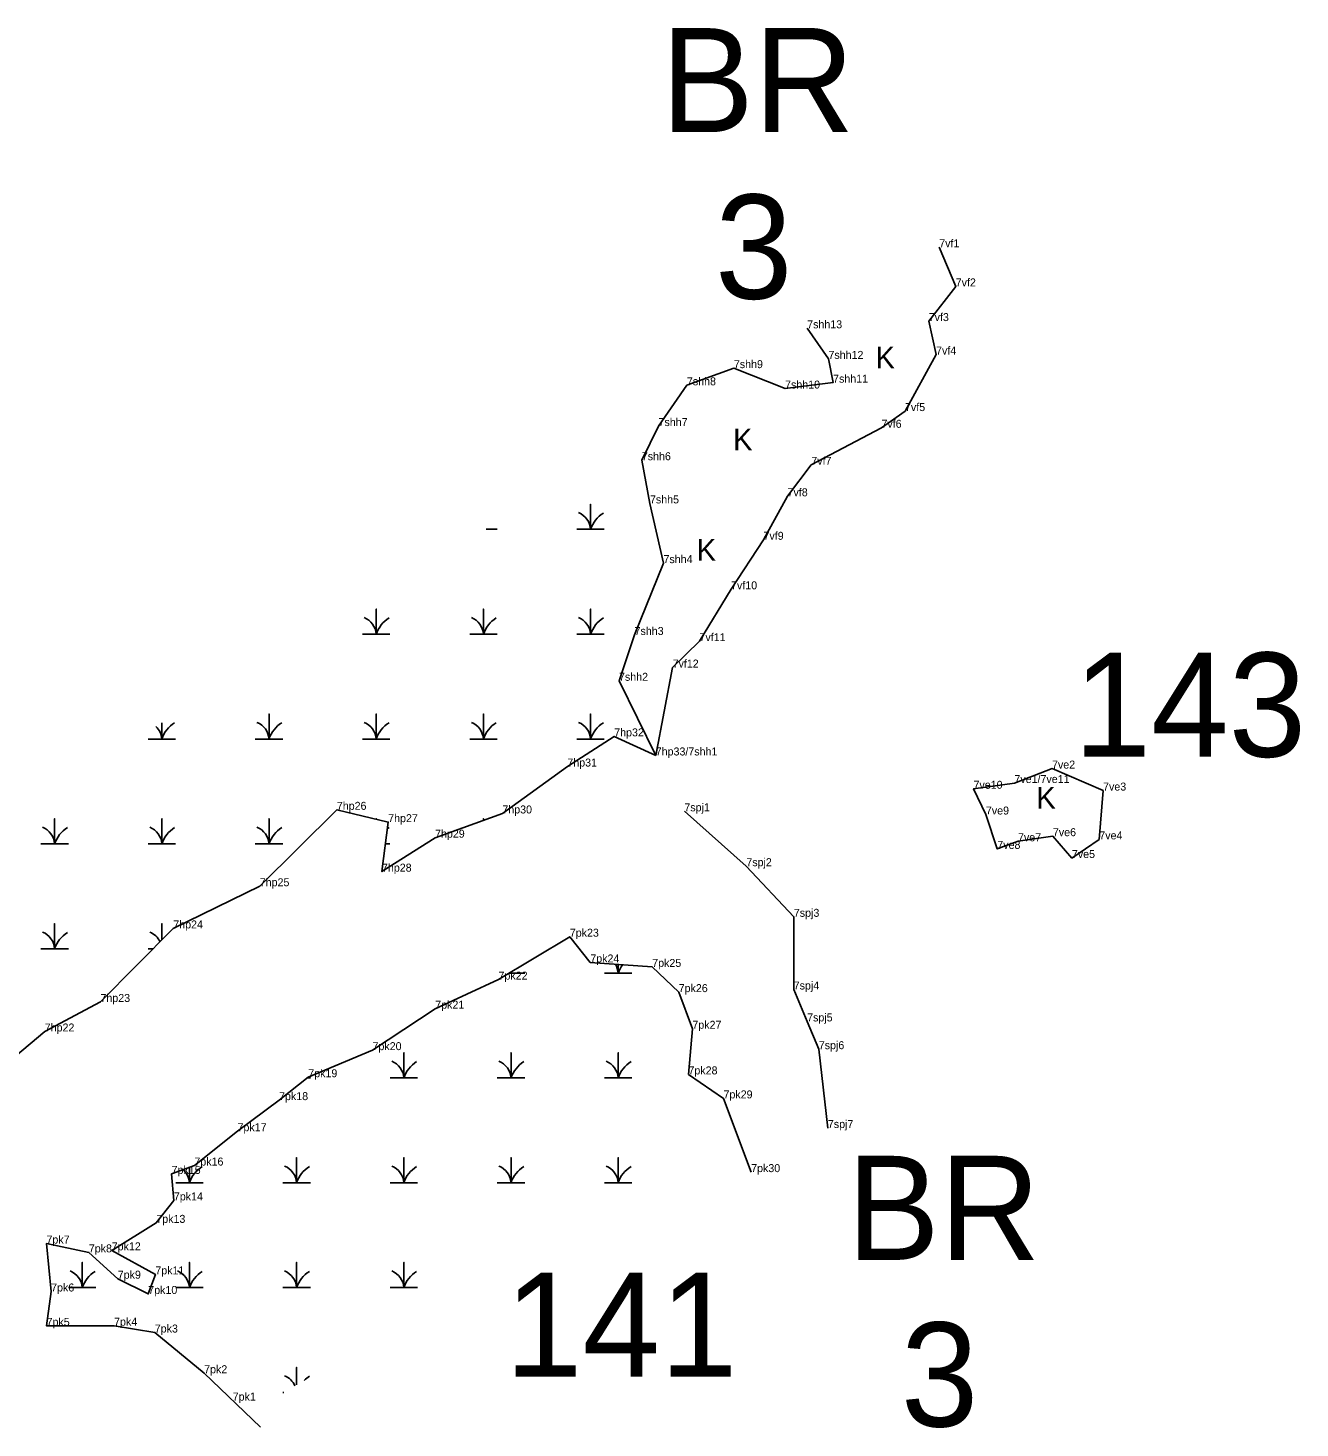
# Model space of a CAD drawing. Extents: x 2072529 to 2268796, y 436423 to 470397.
# Drawn here: x 2166130 to 2166928, y 441934 to 442813 of the extents above; entities that cross this region are included whole.
import ezdxf

# ---------------------------------------------------------------- set-up
doc = ezdxf.new("R2010")
doc.units = 0
for name, color, linetype in [('Default', 7, 'Continuous'), ('Exist Environmental Wetland Boundary', 7, 'Continuous'), ('Exist Environmental Wetland Boundary Cogo Comment', 7, 'Continuous'), ('Exist Environmental Wetland Boundary Cogo Point CELL', 7, 'Continuous'), ('Exist Hydro Jurisdictional Stream or Body of Water NEU Mitigable', 7, 'Continuous'), ('Exist Hydro Jurisdictional Stream or Body of Water NEU Mitigable Cogo Comment', 7, 'Continuous'), ('Exist Hydro Swamp or Marsh', 7, 'Continuous')]:
    doc.layers.add(name, color=color, linetype=linetype)

msp = doc.modelspace()

# ---------------------------------------------------------------- linework, layer by layer
at = {"layer": 'Exist Environmental Wetland Boundary'}
for points in [[(2166523.46, 442356.4), (2166534.04, 442411.56), (2166550.9, 442428.12), (2166570.7, 442460.66), (2166591.07, 442491.73), (2166606.15, 442519.05), (2166621.06, 442538.77), (2166665.06, 442562.01), (2166679.83, 442572.5), (2166699.33, 442607.99), (2166694.72, 442628.97), (2166711.66, 442650.73), (2166701.31, 442675.29)], [(2166103.24, 442152.13), (2166140.13, 442183.19), (2166175.08, 442201.73), (2166220.76, 442247.86), (2166275.02, 442274.32), (2166323.39, 442322.28), (2166355.6, 442314.55), (2166351.69, 442283.5), (2166385.01, 442304.8), (2166427.23, 442320.01), (2166467.99, 442349.45), (2166497.41, 442368.38), (2166523.46, 442356.4)], [(2166275.52, 441934.8), (2166240.13, 441968.75), (2166209.16, 441994.29), (2166183.64, 441998.59), (2166141.28, 441998.44), (2166144.14, 442020.04), (2166141.2, 442050.11), (2166167.79, 442044.56), (2166185.94, 442028.08), (2166205.06, 442018.49), (2166209.52, 442030.78), (2166182.15, 442045.86), (2166210.12, 442063.11), (2166221.13, 442077.18), (2166219.71, 442093.84), (2166234, 442099.06), (2166261.07, 442120.62), (2166287.14, 442140.11), (2166305.45, 442154.48), (2166345.76, 442171.48), (2166385.12, 442197.5), (2166424.81, 442215.74), (2166469.55, 442242.67), (2166482.4, 442226.51), (2166521.24, 442223.71), (2166537.85, 442207.9), (2166546.44, 442184.9), (2166543.98, 442156.26), (2166565.97, 442141.21), (2166583.32, 442094.94)]]:
    msp.add_lwpolyline(points, dxfattribs=at)
msp.add_lwpolyline([(2166748.49, 442339.11), (2166772.08, 442348.17), (2166804.11, 442334.36), (2166801.74, 442303.75), (2166784.54, 442292.04), (2166772.63, 442305.74), (2166750.73, 442302.56), (2166737.74, 442297.78), (2166730.6, 442319.35), (2166722.82, 442335.49)], close=True, dxfattribs=at)
at = {"layer": 'Exist Environmental Wetland Boundary Cogo Point CELL'}
for p, q in [((2166701.31, 442675.29), (2166701.31, 442675.29)), ((2166711.66, 442650.73), (2166711.66, 442650.73)), ((2166618.45, 442624.44), (2166618.45, 442624.44)), ((2166694.72, 442628.97), (2166694.72, 442628.97)), ((2166631.81, 442605.23), (2166631.81, 442605.23)), ((2166699.33, 442607.99), (2166699.33, 442607.99)), ((2166572.48, 442599.44), (2166572.48, 442599.44)), ((2166543.01, 442588.68), (2166543.01, 442588.68)), ((2166604.59, 442586.62), (2166604.59, 442586.62)), ((2166634.71, 442590.33), (2166634.71, 442590.33)), ((2166679.83, 442572.5), (2166679.83, 442572.5)), ((2166525.21, 442563.09), (2166525.21, 442563.09)), ((2166665.06, 442562.01), (2166665.06, 442562.01)), ((2166514.72, 442541.65), (2166514.72, 442541.65)), ((2166621.06, 442538.77), (2166621.06, 442538.77)), ((2166606.15, 442519.05), (2166606.15, 442519.05)), ((2166519.83, 442514.55), (2166519.83, 442514.55)), ((2166591.07, 442491.73), (2166591.07, 442491.73)), ((2166528.31, 442477.08), (2166528.31, 442477.08)), ((2166570.7, 442460.66), (2166570.7, 442460.66)), ((2166510.17, 442432), (2166510.17, 442432)), ((2166550.9, 442428.12), (2166550.9, 442428.12)), ((2166534.04, 442411.56), (2166534.04, 442411.56)), ((2166500.4, 442403.25), (2166500.4, 442403.25)), ((2166497.41, 442368.38), (2166497.41, 442368.38)), ((2166467.99, 442349.45), (2166467.99, 442349.45)), ((2166523.46, 442356.4), (2166523.46, 442356.4)), ((2166523.46, 442356.4), (2166523.46, 442356.4)), ((2166772.08, 442348.17), (2166772.08, 442348.17)), ((2166722.82, 442335.49), (2166722.82, 442335.49)), ((2166748.49, 442339.11), (2166748.49, 442339.11)), ((2166804.11, 442334.36), (2166804.11, 442334.36)), ((2166323.39, 442322.28), (2166323.39, 442322.28)), ((2166355.6, 442314.55), (2166355.6, 442314.55)), ((2166427.23, 442320.01), (2166427.23, 442320.01)), ((2166541.41, 442321.34), (2166541.41, 442321.34)), ((2166730.6, 442319.35), (2166730.6, 442319.35)), ((2166772.63, 442305.74), (2166772.63, 442305.74)), ((2166385.01, 442304.8), (2166385.01, 442304.8)), ((2166737.74, 442297.78), (2166737.74, 442297.78)), ((2166750.73, 442302.56), (2166750.73, 442302.56)), ((2166801.74, 442303.75), (2166801.74, 442303.75)), ((2166784.54, 442292.04), (2166784.54, 442292.04)), ((2166351.69, 442283.5), (2166351.69, 442283.5)), ((2166580.28, 442286.91), (2166580.28, 442286.91)), ((2166275.02, 442274.32), (2166275.02, 442274.32)), ((2166610.1, 442255.15), (2166610.1, 442255.15)), ((2166220.76, 442247.86), (2166220.76, 442247.86)), ((2166469.55, 442242.67), (2166469.55, 442242.67)), ((2166482.4, 442226.51), (2166482.4, 442226.51)), ((2166521.24, 442223.71), (2166521.24, 442223.71)), ((2166424.81, 442215.74), (2166424.81, 442215.74)), ((2166610.01, 442209.54), (2166610.01, 442209.54)), ((2166175.08, 442201.73), (2166175.08, 442201.73)), ((2166537.85, 442207.9), (2166537.85, 442207.9)), ((2166385.12, 442197.5), (2166385.12, 442197.5)), ((2166140.13, 442183.19), (2166140.13, 442183.19)), ((2166546.44, 442184.9), (2166546.44, 442184.9)), ((2166618.43, 442189.5), (2166618.43, 442189.5)), ((2166345.76, 442171.48), (2166345.76, 442171.48)), ((2166625.75, 442172.08), (2166625.75, 442172.08)), ((2166543.98, 442156.26), (2166543.98, 442156.26)), ((2166305.45, 442154.48), (2166305.45, 442154.48)), ((2166287.14, 442140.11), (2166287.14, 442140.11)), ((2166565.97, 442141.21), (2166565.97, 442141.21)), ((2166631.45, 442122.62), (2166631.45, 442122.62)), ((2166261.07, 442120.62), (2166261.07, 442120.62)), ((2166234, 442099.06), (2166234, 442099.06)), ((2166583.32, 442094.94), (2166583.32, 442094.94)), ((2166219.71, 442093.84), (2166219.71, 442093.84)), ((2166221.13, 442077.18), (2166221.13, 442077.18)), ((2166210.12, 442063.11), (2166210.12, 442063.11)), ((2166141.2, 442050.11), (2166141.2, 442050.11)), ((2166167.79, 442044.56), (2166167.79, 442044.56)), ((2166182.15, 442045.86), (2166182.15, 442045.86)), ((2166185.94, 442028.08), (2166185.94, 442028.08)), ((2166209.52, 442030.78), (2166209.52, 442030.78)), ((2166144.14, 442020.04), (2166144.14, 442020.04)), ((2166205.06, 442018.49), (2166205.06, 442018.49)), ((2166141.28, 441998.44), (2166141.28, 441998.44)), ((2166183.64, 441998.59), (2166183.64, 441998.59)), ((2166209.16, 441994.29), (2166209.16, 441994.29)), ((2166240.13, 441968.75), (2166240.13, 441968.75)), ((2166258.04, 441951.57), (2166258.04, 441951.57))]:
    msp.add_line(p, q, dxfattribs=at)
at = {"layer": 'Exist Hydro Jurisdictional Stream or Body of Water NEU Mitigable'}
for points in [[(2166618.45, 442624.44), (2166631.81, 442605.23), (2166634.71, 442590.33), (2166604.59, 442586.62), (2166572.48, 442599.44), (2166543.01, 442588.68), (2166525.21, 442563.09), (2166514.72, 442541.65), (2166519.83, 442514.55), (2166528.31, 442477.08), (2166510.17, 442432), (2166500.4, 442403.25), (2166523.46, 442356.4)], [(2166541.41, 442321.34), (2166580.28, 442286.91), (2166610.1, 442255.15), (2166610.01, 442209.54), (2166618.43, 442189.5), (2166625.75, 442172.08), (2166631.45, 442122.62)]]:
    msp.add_lwpolyline(points, dxfattribs=at)
at = {"layer": 'Exist Hydro Swamp or Marsh'}
for points in [[(2166473.98, 442498.29), (2166482.59, 442498.29), (2166482.59, 442514.07), (2166482.59, 442498.29), (2166491.19, 442498.29)], [(2166417.03, 442498.29), (2166423.94, 442498.29)], [(2166339.48, 442432.49), (2166348.09, 442432.49), (2166348.09, 442448.27), (2166348.09, 442432.49), (2166356.69, 442432.49)], [(2166406.73, 442432.49), (2166415.34, 442432.49), (2166415.34, 442448.27), (2166415.34, 442432.49), (2166423.94, 442432.49)], [(2166473.98, 442432.49), (2166482.59, 442432.49), (2166482.59, 442448.27), (2166482.59, 442432.49), (2166491.19, 442432.49)], [(2166204.98, 442366.69), (2166213.59, 442366.69), (2166213.59, 442376.81)], [(2166213.59, 442376.81), (2166213.59, 442366.69), (2166222.19, 442366.69)], [(2166272.23, 442366.69), (2166280.84, 442366.69), (2166280.84, 442382.47), (2166280.84, 442366.69), (2166289.44, 442366.69)], [(2166339.48, 442366.69), (2166348.09, 442366.69), (2166348.09, 442382.47), (2166348.09, 442366.69), (2166356.69, 442366.69)], [(2166406.73, 442366.69), (2166415.34, 442366.69), (2166415.34, 442382.47), (2166415.34, 442366.69), (2166423.94, 442366.69)], [(2166473.98, 442366.69), (2166482.59, 442366.69), (2166482.59, 442382.47), (2166482.59, 442366.69), (2166491.19, 442366.69)], [(2166137.73, 442300.89), (2166146.34, 442300.89), (2166146.34, 442316.67), (2166146.34, 442300.89), (2166154.94, 442300.89)], [(2166204.98, 442300.89), (2166213.59, 442300.89), (2166213.59, 442316.67), (2166213.59, 442300.89), (2166222.19, 442300.89)], [(2166272.23, 442300.89), (2166280.84, 442300.89), (2166280.84, 442316.67), (2166280.84, 442300.89), (2166289.44, 442300.89)], [(2166348.09, 442316.35), (2166348.09, 442316.67), (2166348.09, 442316.35)], [(2166415.34, 442315.73), (2166415.34, 442316.67), (2166415.34, 442315.73)], [(2166353.88, 442300.89), (2166356.69, 442300.89)], [(2166137.73, 442235.09), (2166146.34, 442235.09), (2166146.34, 442250.87), (2166146.34, 442235.09), (2166154.94, 442235.09)], [(2166213.59, 442240.62), (2166213.59, 442250.87), (2166213.59, 442240.62)], [(2166204.98, 442235.09), (2166208.11, 442235.09)], [(2166431.63, 442219.85), (2166432.66, 442219.85), (2166432.66, 442220.47)], [(2166432.66, 442220.47), (2166432.66, 442219.85), (2166441.26, 442219.85)], [(2166491.31, 442219.85), (2166499.91, 442219.85), (2166499.91, 442225.24)], [(2166499.91, 442225.24), (2166499.91, 442219.85), (2166508.51, 442219.85)], [(2166356.81, 442154.05), (2166365.41, 442154.05), (2166365.41, 442169.83), (2166365.41, 442154.05), (2166374.01, 442154.05)], [(2166424.06, 442154.05), (2166432.66, 442154.05), (2166432.66, 442169.83), (2166432.66, 442154.05), (2166441.26, 442154.05)], [(2166491.31, 442154.05), (2166499.91, 442154.05), (2166499.91, 442169.83), (2166499.91, 442154.05), (2166508.51, 442154.05)], [(2166304.89, 442154.05), (2166306.76, 442154.05)], [(2166289.56, 442088.25), (2166298.16, 442088.25), (2166298.16, 442104.03), (2166298.16, 442088.25), (2166306.76, 442088.25)], [(2166356.81, 442088.25), (2166365.41, 442088.25), (2166365.41, 442104.03), (2166365.41, 442088.25), (2166374.01, 442088.25)], [(2166424.06, 442088.25), (2166432.66, 442088.25), (2166432.66, 442104.03), (2166432.66, 442088.25), (2166441.26, 442088.25)], [(2166491.31, 442088.25), (2166499.91, 442088.25), (2166499.91, 442104.03), (2166499.91, 442088.25), (2166508.51, 442088.25)], [(2166222.31, 442088.25), (2166230.91, 442088.25), (2166230.91, 442097.93)], [(2166230.91, 442097.93), (2166230.91, 442088.25), (2166239.51, 442088.25)], [(2166155.06, 442022.45), (2166163.66, 442022.45), (2166163.66, 442038.23), (2166163.66, 442022.45), (2166172.26, 442022.45)], [(2166222.31, 442022.45), (2166230.91, 442022.45), (2166230.91, 442038.23), (2166230.91, 442022.45), (2166239.51, 442022.45)], [(2166289.56, 442022.45), (2166298.16, 442022.45), (2166298.16, 442038.23), (2166298.16, 442022.45), (2166306.76, 442022.45)], [(2166356.81, 442022.45), (2166365.41, 442022.45), (2166365.41, 442038.23), (2166365.41, 442022.45), (2166374.01, 442022.45)], [(2166298.16, 441961.43), (2166298.16, 441972.43), (2166298.16, 441961.43)], [(2166289.56, 441956.65), (2166290.15, 441956.65)]]:
    msp.add_lwpolyline(points, dxfattribs=at)
for centre, radius, start, end in [((2166470.32, 442497.4), 12.3, 4.14034, 67.53497), ((2166500.83, 442492.23), 19.22, 122.12745, 161.62219), ((2166335.82, 442431.6), 12.3, 4.14034, 67.53497), ((2166366.33, 442426.43), 19.22, 122.12745, 161.62219), ((2166403.07, 442431.6), 12.3, 4.14034, 67.53497), ((2166433.58, 442426.43), 19.22, 122.12745, 161.62219), ((2166470.32, 442431.6), 12.3, 4.14034, 67.53497), ((2166500.83, 442426.43), 19.22, 122.12745, 161.62219), ((2166231.83, 442360.63), 19.22, 122.12745, 161.62219), ((2166268.57, 442365.8), 12.3, 4.14034, 67.53497), ((2166299.08, 442360.63), 19.22, 122.12745, 161.62219), ((2166335.82, 442365.8), 12.3, 4.14034, 67.53497), ((2166366.33, 442360.63), 19.22, 122.12745, 161.62219), ((2166403.07, 442365.8), 12.3, 4.14034, 67.53497), ((2166433.58, 442360.63), 19.22, 122.12745, 161.62219), ((2166470.32, 442365.8), 12.3, 4.14034, 67.53497), ((2166500.83, 442360.63), 19.22, 122.12745, 161.62219), ((2166201.32, 442365.8), 12.3, 4.14034, 45.74119), ((2166134.07, 442300), 12.3, 4.14034, 67.53497), ((2166164.58, 442294.83), 19.22, 122.12745, 161.62219), ((2166201.32, 442300), 12.3, 4.14034, 67.53497), ((2166231.83, 442294.83), 19.22, 122.12745, 161.62219), ((2166268.57, 442300), 12.3, 4.14034, 67.53497), ((2166299.08, 442294.83), 19.22, 122.12745, 161.62219), ((2166366.33, 442294.83), 19.22, 122.12745, 125.82729), ((2166134.07, 442234.2), 12.3, 4.14034, 67.53497), ((2166164.58, 442229.03), 19.22, 122.12745, 161.62219), ((2166201.32, 442234.2), 12.3, 25.30359, 67.53497), ((2166420.39, 442218.96), 12.3, 4.14034, 6.89749), ((2166450.9, 442213.79), 19.22, 159.11027, 161.62219), ((2166487.64, 442218.96), 12.3, 4.14034, 31.43452), ((2166518.15, 442213.79), 19.22, 144.12038, 161.62219), ((2166353.14, 442153.16), 12.3, 4.14034, 67.53497), ((2166383.65, 442147.99), 19.22, 122.12745, 161.62219), ((2166420.39, 442153.16), 12.3, 4.14034, 67.53497), ((2166450.9, 442147.99), 19.22, 122.12745, 161.62219), ((2166487.64, 442153.16), 12.3, 4.14034, 67.53497), ((2166518.15, 442147.99), 19.22, 122.12745, 161.62219), ((2166218.64, 442087.36), 12.3, 4.14034, 47.80076), ((2166249.15, 442082.19), 19.22, 122.12745, 161.62219), ((2166285.89, 442087.36), 12.3, 4.14034, 67.53497), ((2166316.4, 442082.19), 19.22, 122.12745, 161.62219), ((2166353.14, 442087.36), 12.3, 4.14034, 67.53497), ((2166383.65, 442082.19), 19.22, 122.12745, 161.62219), ((2166420.39, 442087.36), 12.3, 4.14034, 67.53497), ((2166450.9, 442082.19), 19.22, 122.12745, 161.62219), ((2166487.64, 442087.36), 12.3, 4.14034, 67.53497), ((2166518.15, 442082.19), 19.22, 122.12745, 161.62219), ((2166151.39, 442021.56), 12.3, 4.14034, 67.53497), ((2166181.9, 442016.39), 19.22, 122.12745, 161.62219), ((2166218.64, 442021.56), 12.3, 4.14034, 67.53497), ((2166249.15, 442016.39), 19.22, 122.12745, 161.62219), ((2166285.89, 442021.56), 12.3, 4.14034, 67.53497), ((2166316.4, 442016.39), 19.22, 122.12745, 161.62219), ((2166353.14, 442021.56), 12.3, 4.14034, 67.53497), ((2166383.65, 442016.39), 19.22, 122.12745, 161.62219), ((2166285.89, 441955.76), 12.3, 24.20487, 67.53497), ((2166316.4, 441950.59), 19.22, 122.12745, 134.7317)]:
    msp.add_arc(centre, radius, start, end, dxfattribs=at)

# ---------------------------------------------------------------- texts
at = {"layer": 'Default'}
for s, p in [('BR', (2166526.72, 442747.53)), ('3', (2166560.65, 442642.99)), ('143', (2166785.7, 442355.57)), ('BR', (2166643.29, 442039.85)), ('141', (2166428.88, 441966.51)), ('3', (2166677.23, 441935.3))]:
    msp.add_text(s, height=65.34, dxfattribs=at).set_placement(p)
at = {"layer": 'Exist Environmental Wetland Boundary Cogo Comment'}
for s, p in [('7vf1', (2166701.31, 442675.29)), ('7vf2', (2166711.66, 442650.73)), ('7vf3', (2166694.72, 442628.97)), ('7vf4', (2166699.33, 442607.99)), ('7vf5', (2166679.83, 442572.5)), ('7vf6', (2166665.06, 442562.01)), ('7vf7', (2166621.06, 442538.77)), ('7vf8', (2166606.15, 442519.05)), ('7vf9', (2166591.07, 442491.73)), ('7vf10', (2166570.7, 442460.66)), ('7vf11', (2166550.9, 442428.12)), ('7vf12', (2166534.04, 442411.56)), ('7hp32', (2166497.41, 442368.38)), ('7hp31', (2166467.99, 442349.45)), ('7ve2', (2166772.08, 442348.17)), ('7ve10', (2166722.82, 442335.49)), ('7ve1/7ve11', (2166748.49, 442339.11)), ('7ve3', (2166804.11, 442334.36)), ('7hp26', (2166323.39, 442322.28)), ('7hp30', (2166427.23, 442320.01)), ('7ve9', (2166730.6, 442319.35)), ('7hp27', (2166355.6, 442314.55)), ('7hp29', (2166385.01, 442304.8)), ('7ve7', (2166750.73, 442302.56)), ('7ve6', (2166772.63, 442305.74)), ('7ve4', (2166801.74, 442303.75)), ('7ve8', (2166737.74, 442297.78)), ('7ve5', (2166784.54, 442292.04)), ('7hp28', (2166351.69, 442283.5)), ('7hp25', (2166275.02, 442274.32)), ('7hp24', (2166220.76, 442247.86)), ('7pk23', (2166469.55, 442242.67)), ('7pk24', (2166482.4, 442226.51)), ('7pk25', (2166521.24, 442223.71)), ('7pk22', (2166424.81, 442215.74)), ('7pk26', (2166537.85, 442207.9)), ('7hp23', (2166175.08, 442201.73)), ('7pk21', (2166385.12, 442197.5)), ('7hp22', (2166140.13, 442183.19)), ('7pk27', (2166546.44, 442184.9)), ('7pk20', (2166345.76, 442171.48)), ('7pk19', (2166305.45, 442154.48)), ('7pk28', (2166543.98, 442156.26)), ('7pk18', (2166287.14, 442140.11)), ('7pk29', (2166565.97, 442141.21)), ('7pk17', (2166261.07, 442120.62)), ('7pk16', (2166234, 442099.06)), ('7pk15', (2166219.71, 442093.84)), ('7pk30', (2166583.32, 442094.94)), ('7pk14', (2166221.13, 442077.18)), ('7pk13', (2166210.12, 442063.11)), ('7pk7', (2166141.2, 442050.11)), ('7pk12', (2166182.15, 442045.86)), ('7pk8', (2166167.79, 442044.56)), ('7pk9', (2166185.94, 442028.08)), ('7pk11', (2166209.52, 442030.78)), ('7pk6', (2166144.14, 442020.04)), ('7pk10', (2166205.06, 442018.49)), ('7pk5', (2166141.28, 441998.44)), ('7pk4', (2166183.64, 441998.59)), ('7pk3', (2166209.16, 441994.29)), ('7pk2', (2166240.13, 441968.75)), ('7pk1', (2166258.04, 441951.57))]:
    msp.add_text(s, height=5, dxfattribs=at).set_placement(p)
at = {"layer": 'Exist Hydro Jurisdictional Stream or Body of Water NEU Mitigable Cogo Comment'}
for s, p in [('7shh13', (2166618.45, 442624.44)), ('7shh9', (2166572.48, 442599.44)), ('7shh12', (2166631.81, 442605.23)), ('7shh11', (2166634.71, 442590.33)), ('7shh8', (2166543.01, 442588.68)), ('7shh10', (2166604.59, 442586.62)), ('7shh7', (2166525.21, 442563.09)), ('7shh6', (2166514.72, 442541.65)), ('7shh5', (2166519.83, 442514.55)), ('7shh4', (2166528.31, 442477.08)), ('7shh3', (2166510.17, 442432)), ('7shh2', (2166500.4, 442403.25)), ('7hp33/7shh1', (2166523.46, 442356.4)), ('7spj1', (2166541.41, 442321.34)), ('7spj2', (2166580.28, 442286.91)), ('7spj3', (2166610.1, 442255.15)), ('7spj4', (2166610.01, 442209.54)), ('7spj5', (2166618.43, 442189.5)), ('7spj6', (2166625.75, 442172.08)), ('7spj7', (2166631.45, 442122.62))]:
    msp.add_text(s, height=5, dxfattribs=at).set_placement(p)
at = {"layer": 'Exist Hydro Swamp or Marsh'}
for p in [(2166661.35, 442599.29), (2166571.98, 442547.95), (2166549.16, 442478.55), (2166762.25, 442323.1)]:
    msp.add_text('K', height=13.6, dxfattribs=at).set_placement(p)

doc.saveas('drawing.dxf')
